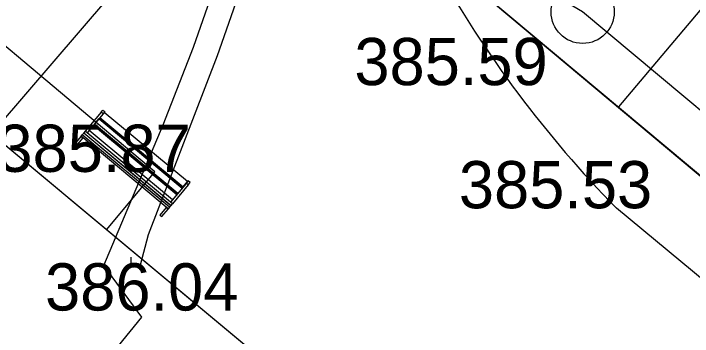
# Model space of a CAD drawing. Extents: x -438233 to -437334, y -1133133 to -1132623.
# Drawn here: x -438124.22 to -438113.45, y -1132977.21 to -1132972.08 of the extents above; entities that cross this region are included whole.
import ezdxf

# ---------------------------------------------------------------- set-up
doc = ezdxf.new("R2010")
doc.units = 0
for name, color, linetype in [('MOBILIÁŘ', 7, 'Continuous'), ('Vrstva 1', 7, 'Continuous'), ('Vrstva 10', 7, 'Continuous'), ('Vrstva 11', 7, 'Continuous'), ('Vrstva 27', 7, 'Continuous'), ('Vrstva 3', 7, 'Continuous'), ('Vrstva 5', 7, 'Continuous'), ('Vrstva 50', 7, 'Continuous'), ('Vrstva 52', 7, 'Continuous'), ('Vrstva 55', 7, 'Continuous')]:
    doc.layers.add(name, color=color, linetype=linetype)

# ---------------------------------------------------------------- blocks, each defined once
blk = doc.blocks.new('A$C6FF56919')
at = {"layer": 'Vrstva 1'}
for p, q in [((-17605, 5482), (-17605, 7031)), ((-401, 7031), (-401, 5482)), ((0, 7031), (-401, 7031)), ((0, 5482), (0, 7031)), ((-18000, 5423), (-18000, 5482)), ((-18000, 5482), (-17605, 5482)), ((-18000, 5423), (0, 5423)), ((-18000, 5108), (-18000, 5423)), ((-17605, 5423), (-17605, 5482)), ((-401, 5482), (0, 5482)), ((-401, 5423), (-401, 5482)), ((0, 5423), (0, 5482)), ((0, 5423), (0, 5108)), ((-18000, 5108), (0, 5108)), ((-18000, 4771), (-18000, 5108)), ((-18000, 4771), (0, 4771)), ((-18000, 4707), (-18000, 4771)), ((0, 4707), (-18000, 4707)), ((-18000, 4707), (-18000, 4365)), ((-18000, 459), (-18000, 4365)), ((-18000, 4365), (0, 4365)), ((-17605, 459), (-17605, 4365)), ((-401, 459), (-401, 4365)), ((0, 5108), (0, 4771)), ((0, 4771), (0, 4707)), ((0, 4365), (0, 4707)), ((0, 459), (0, 4365)), ((-17605, 3703), (-17594, 3703)), ((-17594, 2805), (-17594, 3895)), ((-401, 3703), (-411, 3703)), ((-17605, 2907), (-17594, 2907)), ((-17605, 2901), (-17594, 2901)), ((-17605, 2410), (-17594, 2410)), ((-411, 2805), (-17594, 2805)), ((-17594, 2805), (-17594, 2762)), ((-17594, 2762), (-411, 2762)), ((-17594, 2575), (-411, 2575)), ((-17594, 1475), (-17594, 2575)), ((-9200, 2575), (-9200, 2762)), ((-8799, 2575), (-8799, 2762)), ((-401, 2907), (-411, 2907)), ((-401, 2901), (-411, 2901)), ((-411, 2762), (-411, 2805)), ((-411, 2575), (-411, 1475)), ((-401, 2410), (-411, 2410)), ((-17605, 1608), (-17594, 1608)), ((-17605, 1608), (-17594, 1608)), ((-17605, 1106), (-17594, 1106)), ((-17605, 1106), (-17594, 1106)), ((-17594, 1459), (-17594, 1475)), ((-17594, 1475), (-411, 1475)), ((-411, 1459), (-17594, 1459)), ((-17594, 1245), (-17594, 1256)), ((-17594, 1256), (-411, 1256)), ((-17594, 1245), (-17594, 144)), ((-411, 1245), (-17594, 1245)), ((-9200, 1256), (-9200, 1459)), ((-8800, 1256), (-8800, 1459)), ((-401, 1608), (-411, 1608)), ((-401, 1608), (-411, 1608)), ((-411, 1475), (-411, 1459)), ((-411, 1256), (-411, 1245)), ((-411, 144), (-411, 1245)), ((-401, 1106), (-411, 1106)), ((-401, 1106), (-411, 1106)), ((-18000, 459), (-18000, 0)), ((-17605, 459), (-18000, 459)), ((-18000, 0), (-17605, 0)), ((-17605, 0), (-17605, 459)), ((-17605, 305), (-17594, 305)), ((-17594, 144), (-411, 144)), ((-401, 305), (-411, 305)), ((-401, 459), (0, 459)), ((-401, 0), (-401, 459)), ((0, 0), (-401, 0)), ((0, 459), (0, 0))]:
    blk.add_line(p, q, dxfattribs=at)
for points in [[(-17605, 7031), (-18000, 7031), (-18000, 5482)], [(-17594, 3895), (-411, 3895), (-411, 2805)]]:
    blk.add_lwpolyline(points, dxfattribs=at)

msp = doc.modelspace()

# ---------------------------------------------------------------- linework, layer by layer
at = {"layer": 'Vrstva 1'}
for p, q in [((-438150.612, -1133004.31), (-438119.26, -1132967.803)), ((-438118.649, -1132970.19), (-438104.276, -1132982.231)), ((-438111.734, -1132970.112), (-438114.624, -1132973.562)), ((-438116.314, -1132973.216), (-438116.314, -1132973.216)), ((-438121.978, -1132974.593), (-438121.978, -1132974.593)), ((-438114.656, -1132975.171), (-438114.656, -1132975.171)), ((-438121.222, -1132976.794), (-438121.222, -1132976.794))]:
    msp.add_line(p, q, dxfattribs=at)
at = {"layer": 'Vrstva 10'}
msp.add_lwpolyline([(-438136.916, -1132976.04), (-438130.815, -1132968.777), (-438110.909, -1132985.383), (-438109.206, -1132983.342), (-438101.698, -1132989.616), (-438102.771, -1132990.9), (-438091.189, -1133000.578), (-438097.908, -1133008.583)], close=True, dxfattribs=at)
msp.add_lwpolyline([(-438106.458, -1132981.967), (-438114.656, -1132975.171)], dxfattribs=at)
msp.add_arc((-438101.59, -1132962.409), 18.265, 209.2336, 224.3246, dxfattribs=at)
at = {"layer": 'Vrstva 11'}
msp.add_line((-438122.743, -1132975.51), (-438121.978, -1132974.593), dxfattribs=at)
msp.add_lwpolyline([(-438121.978, -1132974.593), (-438130.965, -1132967.03), (-438137.86, -1132975.253), (-438136.916, -1132976.04)], dxfattribs=at)
at = {"layer": 'Vrstva 27'}
msp.add_circle((-438115.192, -1132972.054), 0.5, dxfattribs=at)
at = {"layer": 'Vrstva 5'}
msp.add_line((-438130.84, -1132968.756), (-438110.909, -1132985.383), dxfattribs=at)
at = {"layer": 'Vrstva 50'}
msp.add_lwpolyline([(-438115.759, -1132966.741), (-438101.366, -1132978.798), (-438104.261, -1132982.253), (-438118.653, -1132970.196)], close=True, dxfattribs=at)
at = {"layer": 'Vrstva 52'}
for points in [[(-438128.855, -1132990.779), (-438128.856, -1132990.91), (-438128.989, -1132990.91), (-438128.989, -1132990.659), (-438128.93, -1132990.596), (-438129.59, -1132987.39), (-438128.59, -1132984.69), (-438123.607, -1132978.703), (-438122.927, -1132977.811), (-438122.184, -1132976.902), (-438122.789, -1132976.078), (-438121.848, -1132973.845), (-438121.368, -1132972.611), (-438119.619, -1132967.617), (-438116.421, -1132963.158), (-438109.667, -1132956.824), (-438099.67, -1132947.487), (-438095.701, -1132943.378), (-438089.916, -1132937.924), (-438083.958, -1132932.455), (-438080.074, -1132928.641), (-438079.488, -1132927.786), (-438078.793, -1132926.015), (-438077.623, -1132919.546)], [(-438077.217, -1132919.546), (-438078.406, -1132926.125), (-438079.132, -1132927.975), (-438079.766, -1132928.899), (-438083.683, -1132932.745), (-438089.644, -1132938.217), (-438095.42, -1132943.663), (-438099.389, -1132947.772), (-438109.394, -1132957.116), (-438116.119, -1132963.423), (-438119.26, -1132967.803), (-438120.993, -1132972.75), (-438122.088, -1132975.591), (-438122.213, -1132976.074), (-438122.355, -1132976.074), (-438122.355, -1132975.945)]]:
    msp.add_lwpolyline(points, dxfattribs=at)
at = {"layer": 'Vrstva 55'}
msp.add_lwpolyline([(-438074.959, -1133013.61), (-438076.856, -1133009.846), (-438083.298, -1132998.719), (-438115.192, -1132972.054), (-438146.469, -1132953.711), (-438176.9, -1132931.48)], dxfattribs=at)

# ---------------------------------------------------------------- block references
at = {"layer": 'MOBILIÁŘ', "xscale": 0.0001, "yscale": 0.00010000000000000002, "rotation": 140.22668670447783}
msp.add_blockref('A$C6FF56919', (-438122.804, -1132973.611), dxfattribs=at)

# ---------------------------------------------------------------- texts
at = {"layer": 'Vrstva 3'}
for s, p in [('385.59 ', (-438118.814, -1132973.216)), ('385.87 ', (-438124.478, -1132974.593)), ('385.53 ', (-438117.156, -1132975.171)), ('386.04 ', (-438123.722, -1132976.794))]:
    msp.add_text(s, height=0.75, dxfattribs=at).set_placement(p)

doc.saveas('drawing.dxf')
